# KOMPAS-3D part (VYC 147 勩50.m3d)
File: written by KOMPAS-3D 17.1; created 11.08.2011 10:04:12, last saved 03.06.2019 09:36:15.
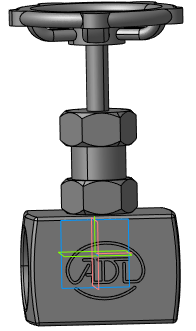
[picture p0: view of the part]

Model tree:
1. Плоскость XY
2. Плоскость ZX
3. Плоскость ZY
4. Ось X
5. Ось Y
6. Ось Z
7. Начало координат
8. Операция без истории:2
